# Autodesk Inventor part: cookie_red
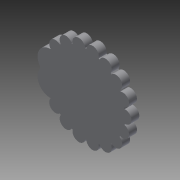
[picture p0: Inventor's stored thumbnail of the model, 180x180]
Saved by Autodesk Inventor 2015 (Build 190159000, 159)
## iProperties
Created: 2017-04
Part Number: cookie_red
Material: Generic
Document SubType Name: Modeling
Designer: mcalderon
Density: 1 g/cm^3
Appearance: Default
Author: mcalderon
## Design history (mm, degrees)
sketch "Sketch1"
  geometry: L1 (25, 0)-(-25, 0); L2 (0, 25)-(0, -25); A1 r 4 centre (25, 0) between (24.68, -3.987) and (24.68, 3.987); A2 r 4 centre (23.492, 8.551) between (24.555, 4.694) and (21.828, 12.188); A3 r 4 centre (19.151, 16.07) between (21.469, 12.81) and (16.343, 18.918); A4 r 4 centre (12.5, 21.651) between (15.793, 19.38) and (8.887, 23.367); A5 r 4 centre (4.341, 24.62) between (8.212, 23.613) and (0.359, 24.997); A6 r 4 centre (-4.341, 24.62) between (-0.359, 24.997) and (-8.212, 23.613); A7 r 4 centre (-12.5, 21.651) between (-8.887, 23.367) and (-15.793, 19.38); A8 r 4 centre (-19.151, 16.07) between (-16.343, 18.918) and (-21.469, 12.81); A9 r 4 centre (-23.492, 8.551) between (-21.828, 12.188) and (-24.555, 4.694); A10 r 4 centre (-25, 0) between (-24.68, 3.987) and (-24.68, -3.987); A11 r 4 centre (-23.492, -8.551) between (-24.555, -4.694) and (-21.828, -12.188); A12 r 4 centre (-19.151, -16.07) between (-21.469, -12.81) and (-16.343, -18.918); A13 r 4 centre (-12.5, -21.651) between (-15.793, -19.38) and (-8.887, -23.367); A14 r 4 centre (-4.341, -24.62) between (-8.212, -23.613) and (-0.359, -24.997); A15 r 4 centre (4.341, -24.62) between (0.359, -24.997) and (8.212, -23.613); A16 r 4 centre (12.5, -21.651) between (8.887, -23.367) and (15.793, -19.38); A17 r 4 centre (19.151, -16.07) between (16.343, -18.918) and (21.469, -12.81); A18 r 4 centre (23.492, -8.551) between (21.828, -12.188) and (24.555, -4.694); A19 r 25 centre (0, 0) between (21.469, -12.81) and (21.828, -12.188); A20 r 25 centre (0, 0) between (15.793, -19.38) and (16.343, -18.918); A21 r 25 centre (0, 0) between (8.212, -23.613) and (8.887, -23.367); A22 r 25 centre (0, 0) between (-0.359, -24.997) and (0.359, -24.997); A23 r 25 centre (0, 0) between (-8.887, -23.367) and (-8.212, -23.613); A24 r 25 centre (0, 0) between (-16.343, -18.918) and (-15.793, -19.38); A25 r 25 centre (0, 0) between (-21.828, -12.188) and (-21.469, -12.81); A26 r 25 centre (0, 0) between (-24.68, -3.987) and (-24.555, -4.694); A27 r 25 centre (0, 0) between (-24.555, 4.694) and (-24.68, 3.987); A28 r 25 centre (0, 0) between (-21.469, 12.81) and (-21.828, 12.188); A29 r 25 centre (0, 0) between (-15.793, 19.38) and (-16.343, 18.918); A30 r 25 centre (0, 0) between (-8.212, 23.613) and (-8.887, 23.367); A31 r 25 centre (0, 0) between (0.359, 24.997) and (-0.359, 24.997); A32 r 25 centre (0, 0) between (8.887, 23.367) and (8.212, 23.613); A33 r 25 centre (0, 0) between (16.343, 18.918) and (15.793, 19.38); A34 r 25 centre (0, 0) between (21.828, 12.188) and (21.469, 12.81); A35 r 25 centre (0, 0) between (24.555, -4.694) and (24.68, -3.987); A36 r 25 centre (0, 0) between (24.68, 3.987) and (24.555, 4.694); 1 further point
  constraints: 74 point on circle, 36 centre point, 4 end point, 1 coincident, 1 perpendicular, 73 other
  dimensions: "d1" = 8 diameter of A1; "d4" = 360 deg dimension on point (0, 0) L1.start (derived)
extrude "Extrusion1" new body sketch "Sketch1" distance "d6" = 5; taper "d7" = 0 deg
sketch "Sketch2"
  geometry: L1 (5.643, -19.187)-(5.643, 19.187); L2 (-31.254, 0)-(33.406, 0); C1 r 8 at (-22.544, 5.431); C2 r 8 at (-22.544, -5.431); A1 r 20 centre (0, 0) between (5.643, -19.187) and (5.643, 19.187); 1 further point
  constraints: 4 end point, 3 centre point, 2 point on circle, 1 coincident, 1 horizontal, 1 symmetric about line, 1 vertical, 1 other
  dimensions: "d9" = 16 diameter of C1
extrude "Extrusion4" join sketch "Sketch2" distance "d14" = 2; taper "d15" = 0 deg
sketch "Sketch5"
  geometry: L1 (-28.509, 0)-(-16.729, 0); L2 (-22.619, -13.304)-(-22.619, 13.431); C1 r 8 at (-22.544, 5.431); C2 r 8 at (-22.544, -5.431); A1 r 8 centre (-22.544, 5.431) between (-16.67, 0) and (-28.418, 0) reference; 1 further point
  constraints: 4 end point, 2 centre point, 1 coincident, 1 horizontal, 1 point on circle, 1 symmetric about line, 1 vertical, 1 other
  dimensions: "d16" = 16 diameter of C1
extrude "Extrusion5" join sketch "Sketch5" distance "d17" = 7; taper "d18" = 0 deg
sketch "Sketch6"
  geometry: 1 further point
sketch "Sketch7"
  geometry: L1 (-16.432, 0)-(6.339, 0); L2 (-16.67, 3.678)-(-16.67, 0); L3 (-16.67, 0)-(-16.407, 3.733); L4 (-16.67, 3.678)-(-16.67, -3.678); 5 further points
  constraints: 8 end point, 2 symmetric about line, 2 vertical, 1 horizontal, 1 point on line, 8 other
extrude "Extrusion6" join sketch "Sketch7" distance "d22" = 2; taper "d23" = 0 deg
body "Solid1"
